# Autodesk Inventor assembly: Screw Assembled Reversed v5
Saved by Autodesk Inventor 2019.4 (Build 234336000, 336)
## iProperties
Created: 2020-06
Part Number: Screw Assembled Reversed v5
Document SubType Name: Assembly
Designer: Administrator
Title: Screw Assembled Reversed v5
Author: Administrator
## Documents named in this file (26)
- c:\worker\convert-fusion-r04\tmp\job-1\85\output\files\12fc5e84-6763-4458-a53a-9d1ae2180744\Screw Assembled Reversed v5_1.iam
- c:\worker\convert-fusion-r04\tmp\job-1\85\output\files\12fc5e84-6763-4458-a53a-9d1ae2180744\Upgraded Screw Harry Edited v15(Mirror).ipt
- c:\worker\convert-fusion-r04\tmp\job-1\85\output\files\12fc5e84-6763-4458-a53a-9d1ae2180744\001 Roller v3(Mirror).ipt
- c:\worker\convert-fusion-r04\tmp\job-1\85\output\files\12fc5e84-6763-4458-a53a-9d1ae2180744\001 Roller v3(Mirror) (1).ipt
- c:\worker\convert-fusion-r04\tmp\job-1\85\output\files\12fc5e84-6763-4458-a53a-9d1ae2180744\001 Roller v3(Mirror) (2).ipt
- c:\worker\convert-fusion-r04\tmp\job-1\85\output\files\12fc5e84-6763-4458-a53a-9d1ae2180744\001 Roller v3(Mirror) (3).ipt
- c:\worker\convert-fusion-r04\tmp\job-1\85\output\files\12fc5e84-6763-4458-a53a-9d1ae2180744\001 Roller v3(Mirror) (4).ipt
- c:\worker\convert-fusion-r04\tmp\job-1\85\output\files\12fc5e84-6763-4458-a53a-9d1ae2180744\001 Roller v3(Mirror) (5).ipt
- c:\worker\convert-fusion-r04\tmp\job-1\85\output\files\12fc5e84-6763-4458-a53a-9d1ae2180744\001 Roller v3(Mirror) (6).ipt
- c:\worker\convert-fusion-r04\tmp\job-1\85\output\files\12fc5e84-6763-4458-a53a-9d1ae2180744\001 Roller v3(Mirror) (7).ipt
- c:\worker\convert-fusion-r04\tmp\job-1\85\output\files\12fc5e84-6763-4458-a53a-9d1ae2180744\001 Roller v3(Mirror) (8).ipt
- c:\worker\convert-fusion-r04\tmp\job-1\85\output\files\12fc5e84-6763-4458-a53a-9d1ae2180744\001 Roller v3(Mirror) (9).ipt
- c:\worker\convert-fusion-r04\tmp\job-1\85\output\files\12fc5e84-6763-4458-a53a-9d1ae2180744\001 Roller v3(Mirror) (10).ipt
- c:\worker\convert-fusion-r04\tmp\job-1\85\output\files\12fc5e84-6763-4458-a53a-9d1ae2180744\001 Roller v3(Mirror) (11).ipt
- c:\worker\convert-fusion-r04\tmp\job-1\85\output\files\12fc5e84-6763-4458-a53a-9d1ae2180744\Component1(Mirror).ipt
- c:\worker\convert-fusion-r04\tmp\job-1\85\output\files\12fc5e84-6763-4458-a53a-9d1ae2180744\Component10(Mirror).ipt
- c:\worker\convert-fusion-r04\tmp\job-1\85\output\files\12fc5e84-6763-4458-a53a-9d1ae2180744\Component2(Mirror).ipt
- c:\worker\convert-fusion-r04\tmp\job-1\85\output\files\12fc5e84-6763-4458-a53a-9d1ae2180744\Component12(Mirror).ipt
- c:\worker\convert-fusion-r04\tmp\job-1\85\output\files\12fc5e84-6763-4458-a53a-9d1ae2180744\Component6(Mirror).ipt
- c:\worker\convert-fusion-r04\tmp\job-1\85\output\files\12fc5e84-6763-4458-a53a-9d1ae2180744\Component3(Mirror).ipt
- c:\worker\convert-fusion-r04\tmp\job-1\85\output\files\12fc5e84-6763-4458-a53a-9d1ae2180744\Component7(Mirror).ipt
- c:\worker\convert-fusion-r04\tmp\job-1\85\output\files\12fc5e84-6763-4458-a53a-9d1ae2180744\Component8(Mirror).ipt
- c:\worker\convert-fusion-r04\tmp\job-1\85\output\files\12fc5e84-6763-4458-a53a-9d1ae2180744\Component11(Mirror).ipt
- c:\worker\convert-fusion-r04\tmp\job-1\85\output\files\12fc5e84-6763-4458-a53a-9d1ae2180744\Component4(Mirror).ipt
- c:\worker\convert-fusion-r04\tmp\job-1\85\output\files\12fc5e84-6763-4458-a53a-9d1ae2180744\Component5(Mirror).ipt
- c:\worker\convert-fusion-r04\tmp\job-1\85\output\files\12fc5e84-6763-4458-a53a-9d1ae2180744\Component9(Mirror).ipt
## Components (25 placed, 25 different names)
1. Upgraded Screw Harry Edited v15(Mirror):1
2. 001 Roller v3(Mirror):1
3. 001 Roller v3(Mirror) (1):1
4. 001 Roller v3(Mirror) (2):1
5. 001 Roller v3(Mirror) (3):1
6. 001 Roller v3(Mirror) (4):1
7. 001 Roller v3(Mirror) (5):1
8. 001 Roller v3(Mirror) (6):1
9. 001 Roller v3(Mirror) (7):1
10. 001 Roller v3(Mirror) (8):1
11. 001 Roller v3(Mirror) (9):1
12. 001 Roller v3(Mirror) (10):1
13. 001 Roller v3(Mirror) (11):1
14. Component1(Mirror):1
15. Component10(Mirror):1
16. Component2(Mirror):1
17. Component12(Mirror):1
18. Component6(Mirror):1
19. Component3(Mirror):1
20. Component7(Mirror):1
21. Component8(Mirror):1
22. Component11(Mirror):1
23. Component4(Mirror):1
24. Component5(Mirror):1
25. Component9(Mirror):1
